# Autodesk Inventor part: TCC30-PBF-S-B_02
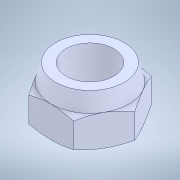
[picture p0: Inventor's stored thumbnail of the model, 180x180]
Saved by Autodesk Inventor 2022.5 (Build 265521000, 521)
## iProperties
Created: 2023-09
Part Number: TCC30-PBF-S-B_02
Material: 一般
Document SubType Name: Modeling
Designer: ImaoCorp
Density: 1 g/cm^3
Appearance: 既定
Author: ImaoCorp
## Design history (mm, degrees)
feature "TCC30-PBF-S-B_02"
node "ソリッド1"
